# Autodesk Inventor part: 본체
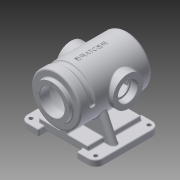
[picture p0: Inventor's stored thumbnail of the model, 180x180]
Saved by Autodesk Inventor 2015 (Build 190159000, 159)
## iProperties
Created: 2015-10
Part Number: 본체
Document SubType Name: Modeling
Designer: mdu
Density: 2.71 g/cm^3
Material: Aluminum 6061
Mass: 4592.12 g
Surface Area: 2715.66 cm^2
Volume: 1694.51 cm^3
Appearance: 기본값(1)
Author: mdu
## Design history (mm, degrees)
sketch "스케치1"
  geometry: L1 (-100, 85)-(-50, 85); L2 (-50, 85)-(-50, -85); L3 (-50, -85)-(-100, -85); L4 (-100, -85)-(-100, 85); L5 (50, 85)-(100, 85); L6 (100, 85)-(100, -85); L7 (100, -85)-(50, -85); L8 (50, -85)-(50, 85); 3 further points
  constraints: 16 end point, 4 parallel, 2 equal length, 2 horizontal, 2 horizontal alignment, 2 midpoint, 2 perpendicular
  dimensions: "d0" = 100 distance between parallel lines of L8 L2; "d1" = 170 distance of L3.end L1.start; "d3" = 200 distance between parallel lines of L6 L4; "d4" = 50 distance from line of point (0, 0) L2 (= 0.5 x d0)
extrude "돌출1" new body sketch "스케치1" distance "d5" = 16; taper "d6" = 0 deg
node "작업 평면1"
sketch "스케치2"
  geometry: L1 (-65, 70)-(65, 70); L2 (65, 70)-(65, -70); L3 (65, -70)-(-65, -70); L4 (-65, -70)-(-65, 70); 3 further points
  constraints: 8 end point, 2 midpoint, 2 parallel, 1 horizontal, 1 horizontal alignment, 1 perpendicular, 1 vertical alignment
  dimensions: "d8" = 130 distance of L2.end L3.end; "d9" = 140 distance of L1.end L2.end
extrude "돌출2" join sketch "스케치2" distance "d10" = 20; taper "d11" = 0 deg
sketch "스케치3"
  geometry: L1 (-100, 110)-(100, 110); L2 (85, 0)-(-85, 0) reference; L3 (100, 110)-(100, 175); L4 (100, 175)-(-90, 175); L5 (-90, 175)-(-90, 156); L6 (-90, 156)-(-100, 156); L7 (-100, 156)-(-100, 110); L8 (90, 110)-(90, 165); L9 (90, 165)-(-75, 165); L10 (-75, 165)-(-75, 110); L11 (-100, 142.5)-(-75, 142.5); 3 further points
  constraints: 20 end point, 5 perpendicular, 4 parallel, 4 point on line, 2 midpoint, 1 horizontal, 1 vertical alignment
  dimensions: "d12" = 110 distance from line of L2 L1.end; "d13" = 200 distance of L1.start L1.end; "d14" = 130 diameter of L4 L1; "d15" = 92 diameter of L6 L1; "d16" = 10 distance of L5.end L6.end; "d42" = 110 diameter of L9 L1; "d43" = 10 distance between parallel lines of L3 L8; "d44" = 25 distance between parallel lines of L10 L7; "d45" = 65 diameter of L11 L1
revolve "회전1" sketch "스케치3" stored, may be unused: angle "d17" = 90 deg
sketch "스케치4"
  geometry: L1 (-50, 70)-(50, 70) reference; L2 (50, -70)-(-50, -70) reference; L3 (-10, 70)-(-10, -70); L4 (10, -70)-(10, 70); 1 further point
  constraints: 4 end point, 4 point on line, 2 perpendicular
  dimensions: "d18" = 20 distance between parallel lines of L4 L3; "d19" = 10 distance from line of point (0, 0) L3
extrude "돌출3" join sketch "스케치4" stored distance "d20" = 10; taper "d21" = 0 deg
node "작업 평면2"
sketch "스케치5"
  geometry: L1 (-50, -8)-(0, -8) reference; L2 (100, -8)-(150, -8) reference; L3 (-40, -8)-(-8.943, -74.601); L4 (140, -8)-(108.943, -74.601); L5 (-50, 8)-(-50, -8) reference; L6 (150, 8)-(150, -8) reference; A1 r 65 centre (50, -102) between (-8.943, -74.601) and (108.943, -74.601) reference; 1 further point
  constraints: 4 end point, 2 point on circle, 2 point on line, 1 equal length
  dimensions: "d23" = 10 distance from line of L3.start L5; "d24" = 10 distance from line of L4.start L6; "d25" = 25 deg angle of L3 L5
feature "리브1" sketch "스케치5" dims "d26" = 1, "d27" = 20, "d28" = 0
node "작업 평면3"
sketch "스케치6"
  geometry: L1 (100, 156)-(100, 64) reference; C1 r 40 at (-25, 110); 2 further points
  constraints: 1 centre point, 1 horizontal alignment, 1 midpoint
  dimensions: "d37" = 80 diameter of C1; "d38" = 125 distance from line of C1.centre L1
extrude "돌출4" join sketch "스케치6" stored distance "d39" = 10; taper "d40" = 0 deg
hole "구멍1" diameter "d48" = 42; stored, may be unused: countersink angle "d52" = 90 deg, drill point angle "d54" = 118 deg; dims "d46" = 10, "d47" = 10, "d49" = 6, "d50" = 52, "d51" = 18, "d53" = 8
sketch "스케치7"
  geometry: C1 r 40 at (0, 0) reference; 2 further points
  constraints: 1 horizontal alignment
  dimensions: "d55" = 32.5 distance of point (32.5, 0) C1.centre
hole "구멍2" sketch "스케치7" at (32.5, 0) diameter "d56" = 3.242; stored, may be unused: countersink angle "d60" = 90 deg, drill point angle "d62" = 118 deg; dims "d57" = 11, "d58" = 52, "d59" = 18, "d61" = 13
sketch "스케치8"
  geometry: C1 r 46 at (0, 0) reference; 2 further points
  constraints: 1 vertical alignment
  dimensions: "d66" = 39 distance of C1.centre point (0, 39)
hole "구멍3" sketch "스케치8" at (0, 39) diameter "d67" = 3.242; stored, may be unused: countersink angle "d71" = 90 deg, drill point angle "d73" = 118 deg; dims "d68" = 11, "d69" = 52, "d70" = 18, "d72" = 13
fillet "모깎기7" dims "d77" = 20, "d78" = 5, "d79" = 3, "d80" = 10, "d107" = 10
fillet "모깎기8" dims "d81" = 3
fillet "모깎기9" dims "d82" = 3
fillet "모깎기10" dims "d83" = 3, "d84" = 0.3
chamfer "모따기1" distance "d85" = 1; stored, may be unused: second distance "d86" = 2, angle "d87" = 45 deg
node "작업 평면4"
sketch "스케치10"
  geometry: 5 further points
  constraints: 2 horizontal alignment, 2 vertical alignment
  dimensions: "d90" = 170 distance of point (85, 70) point (-85, 70); "d91" = 140 distance of point (-85, 70) point (-85, -70); "d92" = 70 vertical distance of point (0, 0) point (-85, -70) (= 0.5 x d91); "d93" = 85 horizontal distance of point (0, 0) point (-85, 70) (= 0.5 x d90)
hole "구멍4" sketch "스케치10" at (-85, 70), (85, 70), (85, -70), (-85, -70) diameter "d94" = 10; stored, may be unused: countersink angle "d98" = 90 deg, drill point angle "d100" = 118 deg; dims "d95" = 6, "d96" = 4, "d97" = 2, "d99" = 8
node "작업 평면5"
sketch "스케치12" dims "d22" = -90
  geometry: L1 (-65, -90)-(65, -90) reference; L2 (65, 85)-(-65, 85) reference; L3 (0, -90)-(0, 85); 3 further points
  constraints: 3 midpoint, 2 end point, 1 coincident, 1 other
feature "엠보싱3" sketch "스케치12" dims "d105" = 1, "d106" = 0
node "작업축1"
sketch "스케치13"
  geometry: L1 (-85, 175)-(90, 175) reference; L2 (-65, 175)-(-50, 175); L3 (-50, 175)-(-50, 170); L4 (-50, 170)-(-65, 170); L5 (-65, 170)-(-65, 175); L6 (-90, 50)-(-90, 170) reference; L7 (-140, 110)-(140, 110) reference; 1 further point
  constraints: 8 end point, 2 parallel, 1 horizontal, 1 perpendicular, 1 point on line
  dimensions: "d108" = 25 distance between parallel lines of L5 L6; "d109" = 15 distance of L3.end L4.end; "d110" = 5 distance of L2.end L3.end
revolve "회전2" sketch "스케치13" stored, may be unused: angle "d111" = 180 deg
fillet "모깎기11" dims "d112" = 5
fillet "모깎기12" dims "d113" = 5
fillet "모깎기13" dims "d114" = 3
node "솔리드1"
mirror "대칭1"
pattern_circular "원형 패턴1" dims angle "d64" = 360 deg
mirror "대칭3"
pattern_circular "원형 패턴2" dims angle "d75" = 360 deg
other parameters: "d7" = 8, "d36" = -75
